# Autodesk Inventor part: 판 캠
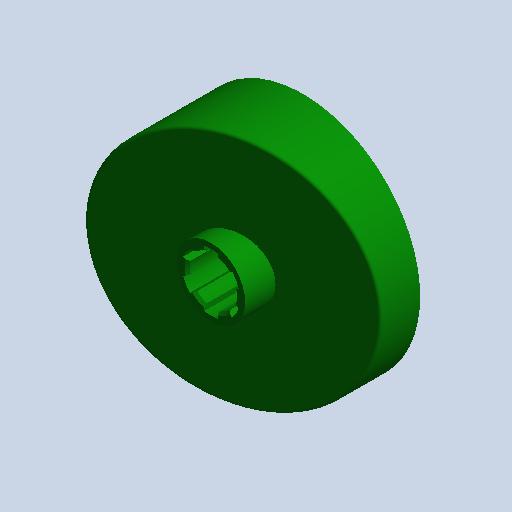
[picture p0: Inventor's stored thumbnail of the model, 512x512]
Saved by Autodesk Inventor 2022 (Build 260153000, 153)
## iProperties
Created: 2021-07
Part Number: 판 캠
Document SubType Name: 모델링
Designer: mdu
Material: 알루미늄 6061
Density: 2.71 g/cm^3
Mass: 235.299 g
Surface Area: 331.301 cm^2
Volume: 86.8262 cm^3
Appearance: 진녹색
변환 표준: STEP AP214IS
파일 이름: C:\Users\SeoGD\Desktop\?쒗뿕\??stp
전처리기: Build: 253, Release: 2010 SP1 - Date: Wed 07/29/2009
전송 단위: 밀리미터
불확실성: 0.01
Author: mdu
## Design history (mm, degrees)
node "작업 평면4"
sketch "스케치1"
  geometry: C1 r 44.5 at (0, 0); 1 further point
  constraints: 1 centre point, 1 coincident
  dimensions: "d25" = 89 diameter of C1
extrude "돌출1" new body sketch "스케치1" distance "d1" = 40; taper "d2" = 0 deg
sketch "스케치2"
  geometry: L1 (-44.5, 15)-(44.5, 38.847); L2 (-44.5, 0)-(-44.5, 40) reference; L3 (-44.5, 40)-(44.5, 40) reference; L4 (44.5, 0)-(44.5, 40) reference; 1 further point
  constraints: 2 end point, 2 point on line
  dimensions: "d26" = 15 distance of L2.start L1.start; "d27" = 75 deg angle of L1 L2
extrude "돌출2" cut sketch "스케치2" extent not by distance; stored distance "d5" = 40; taper "d6" = 0 deg
node "작업 평면1"
sketch "스케치3"
  geometry: C1 r 13 at (0, 0); 1 further point
  constraints: 1 centre point, 1 coincident
  dimensions: "d9" = 26 diameter of C1
extrude "돌출3" join sketch "스케치3" distance "d10" = 38; taper "d11" = 0 deg
hole "구멍1" diameter "d14" = 18; stored, may be unused: countersink angle "d18" = 90 deg, drill point angle "d20" = 118 deg; dims "d12" = 10, "d13" = 10, "d15" = 6, "d16" = 4, "d17" = 2, "d19" = 8
feature "쉘2" dims "d29" = 5
sketch "스케치6"
  geometry: C1 r 17.5 at (0, 0); C2 r 14 at (0, 0) reference; 1 further point
  constraints: 1 centre point, 1 coincident
  dimensions: "d28" = 35 diameter of C1
extrude "돌출4" join sketch "스케치6" stored distance "d30" = 38; taper "d31" = 0 deg
fillet "모깎기1" dims "d32" = 3
chamfer "모따기1" distance "d21" = 1; stored, may be unused: second distance "d22" = 2, angle "d23" = 45 deg
sketch "스케치7"
  geometry: L1 (-12.374, 12.374)-(-27.931, 27.931); A1 r 39.5 centre (0, 0) between (-27.931, 27.931) and (0, 39.5) reference; 2 further points
  constraints: 2 end point, 2 point on circle, 1 point on line, 1 vertical alignment, 2 other
  dimensions: "d33" = 45 deg dimension on point (0, 0) L1.start A1.end
feature "리브1" sketch "스케치7" dims "d34" = 5, "d35" = 1, "d36" = 0
fillet "모깎기2" dims "d37" = 3
sketch "스케치8"
  geometry: L1 (2.5, 10.712)-(2.5, 8.646); L2 (-2.5, 10.712)-(-2.5, 8.646); A1 r 11 centre (0, 0) between (2.5, 10.712) and (-2.5, 10.712); A2 r 9 centre (0, 0) between (2.5, 8.646) and (-2.5, 8.646) reference; 1 further point
  constraints: 4 end point, 4 point on circle, 2 parallel, 1 centre point, 1 coincident, 1 vertical
  dimensions: "d41" = 22 diameter of A1; "d42" = 5 distance between parallel lines of L1 L2
extrude "돌출5" cut sketch "스케치8" extent not by distance; stored distance "d43" = 38; taper "d44" = 0 deg
fillet "모깎기3" dims "d48" = 1
node "솔리드1"
node "솔리드 본체"
node "곡면 본체"
pattern_circular "원형 패턴1" dims angle "d39" = 360 deg
pattern_circular "원형 패턴2" dims angle "d46" = 360 deg
node "솔리드2"
